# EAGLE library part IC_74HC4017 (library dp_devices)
Decade counter
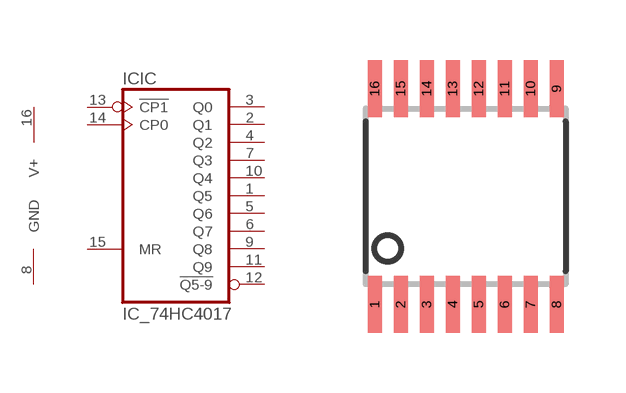
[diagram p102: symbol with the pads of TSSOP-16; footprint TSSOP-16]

Designator prefix IC; gates IC=74HC4017 SUPPLY=SUPPLY

## IC_74HC4017-TSSOP-16  [TSSOP-16]
1  IC:Q5  out
2  IC:Q1  out
3  IC:Q0  out
4  IC:Q2  out
5  IC:Q6  out
6  IC:Q7  out
7  IC:Q3  out
8  SUPPLY:GND  sup
9  IC:Q8  out
10  IC:Q4  out
11  IC:Q9  out
12  IC:!Q5-9  out
13  IC:!CP1  in
14  IC:CP0  in
15  IC:MR  in
16  SUPPLY:V+  sup

## Footprint TSSOP-16 (pad centres in mm)
smd 0.35 x 1.43: 1 -2.275,-2.7; 2 -1.625,-2.7; 3 -0.975,-2.7; 4 -0.325,-2.7; 5 0.325,-2.7; 6 0.975,-2.7; 7 1.625,-2.7; 8 2.275,-2.7; 9 2.275,2.7; 10 1.625,2.7; 11 0.975,2.7; 12 0.325,2.7; 13 -0.325,2.7; 14 -0.975,2.7; 15 -1.625,2.7; 16 -2.275,2.7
